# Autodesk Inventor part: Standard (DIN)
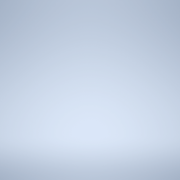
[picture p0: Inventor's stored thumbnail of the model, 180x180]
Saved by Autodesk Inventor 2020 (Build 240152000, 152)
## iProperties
Created: 2019-02
Part Number: Standard (DIN)
Material: Ogólny
Document SubType Name: Modeling
Density: 1 g/cm^3
Appearance: Domyślna
Catalog Web Link: www.expertbooks.pl
Designer: F.Stasiak
Manager: www.cadconsulting.pl
Company: Fabian Stasiak CAD Consulting
Subject: Zbiór ćwiczeń. Autodesk Inventor 2020. Kurs Professional
Author: F.Stasiak
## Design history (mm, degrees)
